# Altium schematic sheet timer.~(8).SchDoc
size A4
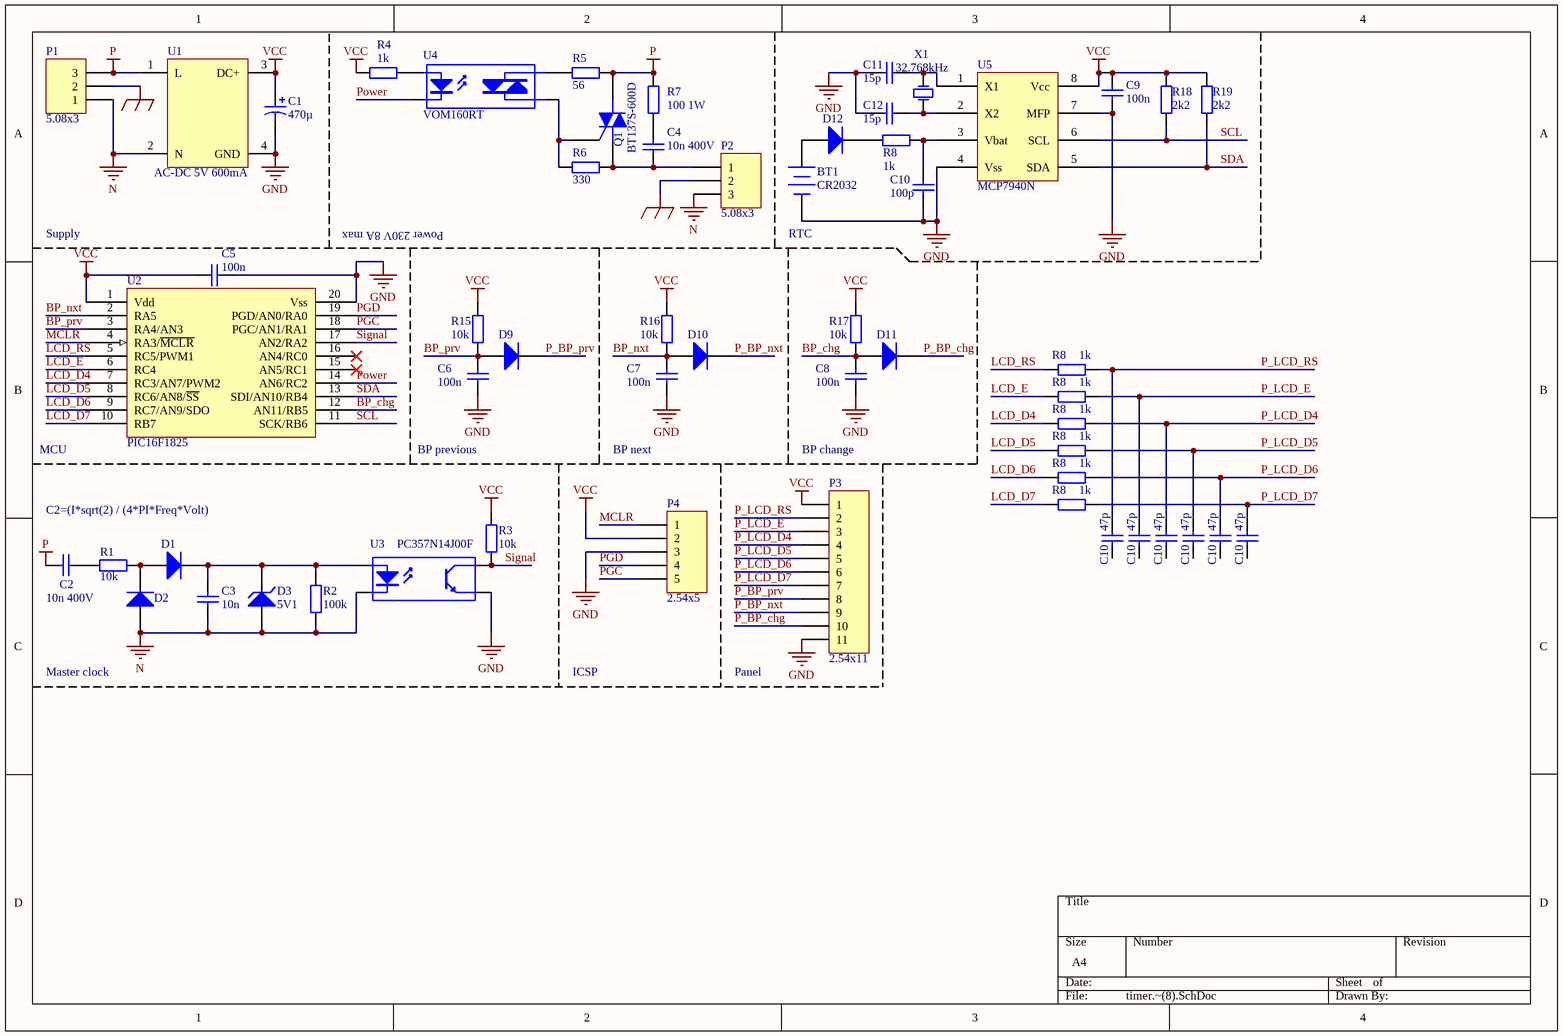
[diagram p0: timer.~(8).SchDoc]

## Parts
(Parts that share a designator on the sheet are numbered #1, #2 ... from top to bottom, then left to right.)
BT1  CR2032  [BAT_2032]
C1  470µ  [CAP_6.3x2.5]
C2  10n 400V  [C1812]
C3  10n  [C0805]
C4  10n 400V  [C1812]
C5  100n  [C0805]
C6  100n  [C0805]
C7  100n  [C0805]
C8  100n  [C0805]
C9  100n  [C0805]
C10#1  100p  [C0805]
C10#2  47p  [C0805]
C10#3  47p  [C0805]
C10#4  47p  [C0805]
C10#5  47p  [C0805]
C10#6  47p  [C0805]
C10#7  47p  [C0805]
C11  15p  [C0805]
C12  15p  [C0805]
D1  MBR0520LT  [SOD-123]  (value not drawn)
D2  MBR0520LT  [SOD-123]  (value not drawn)
D3  5V1  [SOD-123]
D9  MBR0520LT  [SOD-123]  (value not drawn)
D10  MBR0520LT  [SOD-123]  (value not drawn)
D11  MBR0520LT  [SOD-123]  (value not drawn)
D12  MBR0520LT  [SOD-123]  (value not drawn)
P1  5.08x3  [Bornier 5.08x3]
P2  5.08x3  [Bornier 5.08x3]
P3  2.54x11  [HDR1X11]
P4  2.54x5  [HDR1X5]
Q1  BT137S-600D  [DPAK]
R1  10k  [R1206]
R2  100k  [R0805]
R3  10k  [R0805]
R4  1k  [R0805]
R5  56  [R1206]
R6  330  [R1206]
R7  100 1W  [R2512]
R8#1  1k  [R0805]
R8#2  1k  [R0805]
R8#3  1k  [R0805]
R8#4  1k  [R0805]
R8#5  1k  [R0805]
R8#6  1k  [R0805]
R8#7  1k  [R0805]
R15  10k  [R0805]
R16  10k  [R0805]
R17  10k  [R0805]
R18  2k2  [R0805]
R19  2k2  [R0805]
U1  AC-DC 5V 600mA  [AC-DC 3W]
U2  PIC16F1825  [SOIC-20]
U3  PC357N14J00F  [OPTO_PC357N14J00F]
U4  VOM160RT  [OPTO_VOM160RT]
U5  MCP7940N  [SOIC-8]
X1  32.768kHz  [R38]

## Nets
Earth: P1.2 P2.2
GND: BT1.2(-) C1.2 C5.1 C6.2 C7.2 C8.2 C9.2 C10#1.2 C11.2 C12.2 P3.11 P4.3 U1.4(GND) U2.20(Vss) U3.3(E) U5.4(Vss) U5.7(MFP)
N: C3.2 D2.1(A) D3.1(A) P1.1 P2.3 R2.2 U1.2(N) U3.2(K)
P: C2.1 P1.3 Q1.2(M2) R5.1 R7.1 U1.1(L)
VCC: C1.1 C5.2 C9.1 P3.1 P4.2 R3.2 R4.2 R15.2 R16.2 R17.2 R18.1 R19.1 U1.3(DC+) U2.1(Vdd) U5.8(Vcc)
BP_chg: C8.1 D11.1(A) R17.1 U2.12(AN11/RB5)
BP_nxt: C7.1 D10.1(A) R16.1 U2.2(RA5)
BP_prv: C6.1 D9.1(A) R15.1 U2.3(RA4/AN3)
LCD_D4: R8#4.1 U2.7(RC3/AN7/PWM2)
LCD_D5: R8#5.1 U2.8(RC6/AN8/~{SS})
LCD_D6: R8#6.1 U2.9(RC7/AN9/SDO)
LCD_D7: R8#7.1 U2.10(RB7)
LCD_E: R8#3.1 U2.6(RC4)
LCD_RS: R8#2.1 U2.5(RC5/PWM1)
MCLR: P4.1 U2.4(RA3/~{MCLR})
P_BP_chg: D11.2(K) P3.10
P_BP_nxt: D10.2(K) P3.9
P_BP_prv: D9.2(K) P3.8
P_LCD_D4: C10#4.1 P3.4 R8#4.2
P_LCD_D5: C10#5.1 P3.5 R8#5.2
P_LCD_D6: C10#6.1 P3.6 R8#6.2
P_LCD_D7: C10#7.1 P3.7 R8#7.2
P_LCD_E: C10#3.1 P3.3 R8#3.2
P_LCD_RS: C10#2.1 P3.2 R8#2.2
PGC: P4.5 U2.18(PGC/AN1/RA1)
PGD: P4.4 U2.19(PGD/AN0/RA0)
Power: U2.14(AN6/RC2) U4.2(K)
SCL: R18.2 U2.11(SCK/RB6) U5.6(SCL)
SDA: R19.2 U2.13(SDI/AN10/RB4) U5.5(SDA)
Signal: R3.1 U2.17(AN2/RA2) U3.4(C)
NetBT1_1: BT1.1(+) D12.1(A)
NetC2_2: C2.2 R1.2
NetC3_1: C3.1 D1.2(K) D3.2(K) R2.1 U3.1(A)
NetC4_1: C4.1 R7.2
NetC4_2: C4.2 P2.1 Q1.1(M1) R6.1
NetC10#1_1: C10#1.1 R8#1.2 U5.3(Vbat)
NetC11_1: C11.1 U5.1(X1) X1.1(OSC1)
NetC12_1: C12.1 U5.2(X2) X1.2(OSC2)
NetD1_1: D1.1(A) D2.2(K) R1.1
NetD12_2: D12.2(K) R8#1.1
NetQ1_3: Q1.3(G) R6.2 U4.4(A/K)
NetR4_1: R4.1 U4.1(A)
NetR5_2: R5.2 U4.3(A/K)

Not connected (* = marked no-connect by the designer): C10#2 2; C10#3 2; C10#4 2; C10#5 2; C10#6 2; C10#7 2; U2 15(AN5/RC1)* 16(AN4/RC0)*

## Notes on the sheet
- Supply
- Power 230V 8A max
- (near BT1) RTC
- MCU
- C2=(I*sqrt(2) / (4*PI*Freq*Volt)
- BP previous
- BP next
- BP change
- Master clock
- ICSP
- Panel

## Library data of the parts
BT1 = Battery: Multicell Battery; pin to pad: 1>+ 2>-
C1 = Cap Pol1: Polarized Capacitor (Radial)
C2-C9 C10#1-C10#7 C11 C12 = Cap: Capacitor
D1 D2 D9-D12 = Diode 1N4001: 1 Amp General Purpose Rectifier
D3 = D Zener: Zener Diode
P1 P2 = Header 3: Header, 3-Pin
P3 = Header 11: Header, 11-Pin
P4 = Header 5: Header, 5-Pin
Q1 = Triac: Silicon Bidirectional Triode Thyristor; Note: Pin 2 is electrically connected to Pin 4 (TAB)
R1-R7 R8#1-R8#7 R15-R19 = Res2: Resistor
U1 = AC-DC
U2 = PIC16F1829
U3 = Optoisolator1: 4-Pin Phototransistor Optocoupler
U4 = Opto TRIAC: Opto-Triac; pin to pad: 3>4 4>3
U5 = RTC- MCP7940N
X1 = XTAL: Crystal Oscillator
